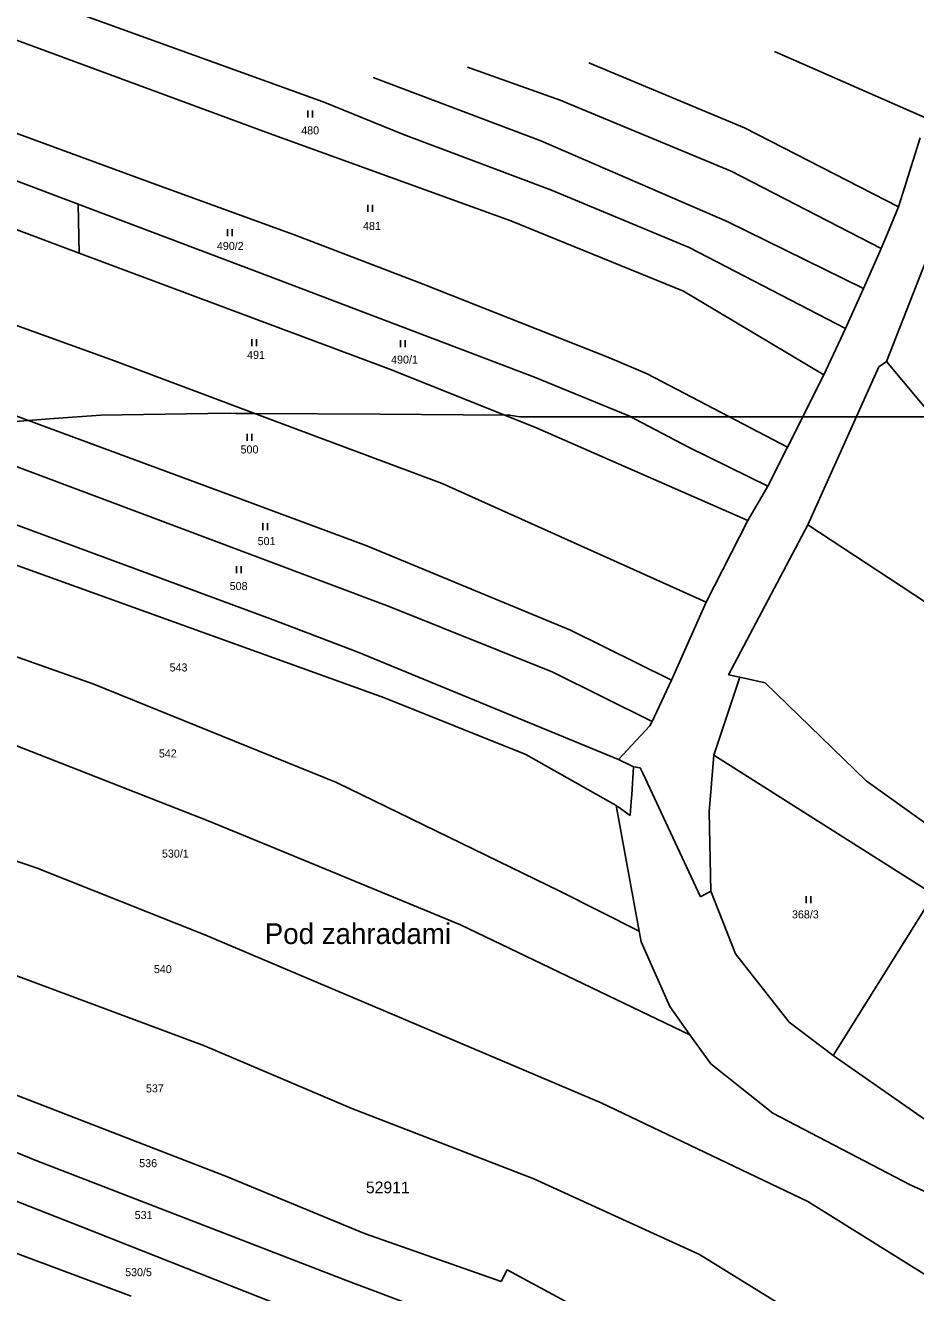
# Model space of a CAD drawing. Extents: x -749173 to -746119, y -1132678 to -1130338.
# Drawn here: x -748168.2 to -747979.1, y -1130971 to -1130701.9 of the extents above; entities that cross this region are included whole.
import ezdxf

# ---------------------------------------------------------------- set-up
doc = ezdxf.new("R2010")
doc.units = 0
for name, color, linetype in [('Vrstva 1', 7, 'Continuous'), ('Vrstva 15', 7, 'Continuous'), ('Vrstva 18', 7, 'Continuous'), ('Vrstva 25', 7, 'Continuous'), ('Vrstva 52', 7, 'Continuous'), ('Vrstva 53', 7, 'Continuous'), ('Vrstva 6', 7, 'Continuous')]:
    doc.layers.add(name, color=color, linetype=linetype)

msp = doc.modelspace()

# ---------------------------------------------------------------- linework, layer by layer
at = {"layer": 'Vrstva 1'}
for points in [[(-747978.13, -1130725.78), (-747981.47, -1130736.34)], [(-747968.32, -1130729.96), (-747985.28, -1130773.23)], [(-747981.47, -1130736.34), (-747982.76, -1130740.42)], [(-747982.76, -1130740.42), (-747984.75, -1130745.21)], [(-747984.75, -1130745.21), (-747986.44, -1130749.26)], [(-747986.44, -1130749.26), (-747987.1, -1130750.86)], [(-747987.1, -1130750.86), (-747990.16, -1130757.72)], [(-747990.16, -1130757.72), (-747994, -1130766.24)], [(-747994, -1130766.24), (-747998.62, -1130776.08)], [(-748001.98, -1130807.92), (-747986.9, -1130774.39)], [(-747986.9, -1130774.39), (-747985.28, -1130773.23)], [(-747937.23, -1130830.7), (-747985.28, -1130773.23)], [(-747998.62, -1130776.08), (-748006.3, -1130791.42)], [(-748006.3, -1130791.42), (-748010.51, -1130799.75)], [(-748116.18, -1130827.89), (-748206.22, -1130794.61)], [(-748010.51, -1130799.75), (-748014.77, -1130807.03)], [(-748023.6, -1130824.38), (-748014.77, -1130807.03)], [(-748001.98, -1130807.92), (-748018.82, -1130839.78)], [(-747959.65, -1130835.75), (-748001.98, -1130807.92)], [(-748171.55, -1130816.01), (-748091.95, -1130844.69)], [(-748023.6, -1130824.38), (-748030.93, -1130840.93)], [(-748097.77, -1130834.89), (-748116.18, -1130827.89)], [(-748042.25, -1130857.8), (-748097.77, -1130834.89)], [(-748030.93, -1130840.93), (-748035.09, -1130849.72)], [(-748016.47, -1130840.3), (-748021.96, -1130856.83)], [(-748018.82, -1130839.78), (-748016.47, -1130840.3)], [(-748016.47, -1130840.3), (-748011.06, -1130841.51)], [(-748011.06, -1130841.51), (-747989.61, -1130862.33)], [(-748091.95, -1130844.69), (-748061.9, -1130856.72)], [(-748035.09, -1130849.72), (-748035.54, -1130850.63)], [(-748035.54, -1130850.63), (-748042.25, -1130857.8)], [(-748061.9, -1130856.72), (-748042.73, -1130867.52)], [(-748039.61, -1130859.03), (-748042.25, -1130857.8)], [(-748022.97, -1130868.9), (-748021.96, -1130856.83)], [(-748021.96, -1130856.83), (-747975.23, -1130886.46)], [(-748039.02, -1130859.3), (-748039.61, -1130859.03)], [(-748039.41, -1130865.27), (-748039.02, -1130859.3)], [(-748039.02, -1130859.3), (-748037.61, -1130859.57)], [(-748037.61, -1130859.57), (-748037.08, -1130860.71)], [(-748037.08, -1130860.71), (-748024.8, -1130886.92)], [(-747989.61, -1130862.33), (-747963.27, -1130881.1)], [(-748039.51, -1130866.71), (-748039.41, -1130865.27)], [(-748042.73, -1130867.52), (-748037.84, -1130894.2)], [(-748042.73, -1130867.52), (-748042.31, -1130867.82)], [(-748042.31, -1130867.82), (-748039.71, -1130869.68)], [(-748039.71, -1130869.68), (-748039.51, -1130866.71)], [(-748022.6, -1130885.76), (-748022.97, -1130868.9)], [(-748024.8, -1130886.92), (-748022.6, -1130885.76)], [(-748017.39, -1130899.05), (-748022.6, -1130885.76)], [(-747975.23, -1130886.46), (-747996.61, -1130920.66)], [(-748037.84, -1130894.2), (-748037.41, -1130896.52)], [(-748037.41, -1130896.52), (-748031.35, -1130910.26)], [(-748005.97, -1130913.58), (-748017.39, -1130899.05)], [(-748031.35, -1130910.26), (-748027.06, -1130916.24)], [(-747996.61, -1130920.66), (-748005.97, -1130913.58)], [(-748027.06, -1130916.24), (-748022.64, -1130922.41)], [(-748009.46, -1130932.87), (-748022.64, -1130922.41)], [(-747996.61, -1130920.66), (-747974.9, -1130935.77)], [(-747980.23, -1130948.11), (-748009.46, -1130932.87)], [(-747943.32, -1130964.83), (-747980.23, -1130948.11)]]:
    msp.add_lwpolyline(points, dxfattribs=at)
at = {"layer": 'Vrstva 25'}
for p, q in [((-748108.25, -1130719.95), (-748108.25, -1130721.45)), ((-748107.25, -1130721.45), (-748107.25, -1130719.95)), ((-748095.46, -1130739.95), (-748095.46, -1130741.45)), ((-748094.46, -1130741.45), (-748094.46, -1130739.95)), ((-748125.27, -1130745.17), (-748125.27, -1130746.67)), ((-748124.27, -1130746.67), (-748124.27, -1130745.17)), ((-748120.1, -1130768.49), (-748120.1, -1130769.99)), ((-748119.1, -1130769.99), (-748119.1, -1130768.49)), ((-748088.55, -1130768.71), (-748088.55, -1130770.21)), ((-748087.55, -1130770.21), (-748087.55, -1130768.71)), ((-748121.1, -1130788.58), (-748121.1, -1130790.08)), ((-748120.1, -1130790.08), (-748120.1, -1130788.58)), ((-748117.77, -1130807.56), (-748117.77, -1130809.06)), ((-748116.77, -1130809.06), (-748116.77, -1130807.56)), ((-748123.4, -1130816.72), (-748123.4, -1130818.22)), ((-748122.4, -1130818.22), (-748122.4, -1130816.72)), ((-748002.37, -1130886.81), (-748002.37, -1130888.31)), ((-748001.37, -1130888.31), (-748001.37, -1130886.81))]:
    msp.add_line(p, q, dxfattribs=at)
at = {"layer": 'Vrstva 52'}
for points in [[(-748092.85, -1130784.45), (-748119.44, -1130784.28), (-748123.54, -1130784.26), (-748124.94, -1130784.25), (-748152.19, -1130784.62), (-748162.19, -1130785.36), (-748167.62, -1130785.76), (-748182.96, -1130786.89), (-748191.61, -1130787.52), (-748204.04, -1130788.43), (-748210, -1130788.87), (-748213.91, -1130789.71), (-748217.19, -1130790.42), (-748232.12, -1130793.62), (-748249.33, -1130798.12), (-748251.25, -1130798.62), (-748258.98, -1130801.59), (-748265.99, -1130804.29), (-748269.12, -1130805.5)], [(-747975.44, -1130785), (-747991.67, -1130785), (-748003.09, -1130785), (-748018.64, -1130785), (-748039.56, -1130785), (-748063.25, -1130785), (-748065.37, -1130784.62), (-748065.97, -1130784.62), (-748066.42, -1130784.62), (-748092.85, -1130784.45)]]:
    msp.add_lwpolyline(points, dxfattribs=at)
at = {"layer": 'Vrstva 6'}
for points in [[(-748116.35, -1130724.81), (-748185.93, -1130699.2)], [(-748104.99, -1130718.13), (-748160.68, -1130697.99)], [(-748009.08, -1130707.45), (-747977.16, -1130721.44)], [(-748015.48, -1130723.6), (-748048.51, -1130709.83)], [(-748094.37, -1130712.93), (-748058.72, -1130726.42)], [(-748074.3, -1130710.72), (-748054.6, -1130717.75)], [(-748192.08, -1130716.76), (-748141.67, -1130735.26)], [(-748087.93, -1130725.07), (-748104.99, -1130718.13)], [(-748054.6, -1130717.75), (-748018.25, -1130732.85)], [(-747982.76, -1130740.42), (-748015.48, -1130723.6)], [(-748065.1, -1130743.37), (-748116.35, -1130724.81)], [(-748056.46, -1130736.89), (-748087.93, -1130725.07)], [(-748058.72, -1130726.42), (-748019.1, -1130743.55)], [(-748172.71, -1130733.91), (-748157.04, -1130739.82)], [(-748018.25, -1130732.85), (-747986.44, -1130749.26)], [(-748141.67, -1130735.26), (-748110.72, -1130746.5)], [(-748027.2, -1130749.04), (-748056.46, -1130736.89)], [(-748186.46, -1130739.14), (-748156.81, -1130750.21)], [(-748157.04, -1130739.82), (-748116.12, -1130755.25)], [(-748157.04, -1130739.82), (-748156.81, -1130750.21)], [(-748028.39, -1130758.32), (-748065.1, -1130743.37)], [(-748019.1, -1130743.55), (-747990.16, -1130757.72)], [(-748110.72, -1130746.5), (-748083.73, -1130756.86)], [(-748156.81, -1130750.21), (-748090.98, -1130774.79)], [(-747994, -1130766.24), (-748027.2, -1130749.04)], [(-748116.12, -1130755.25), (-748060.06, -1130776.6)], [(-748149.26, -1130773.11), (-748192.95, -1130757.36)], [(-748083.73, -1130756.86), (-748044.13, -1130772.48)], [(-747998.62, -1130776.08), (-748028.39, -1130758.32)], [(-748124.83, -1130801.55), (-748198.84, -1130774.24)], [(-748117.42, -1130785.04), (-748149.26, -1130773.11)], [(-748090.98, -1130774.79), (-748059.97, -1130787.2)], [(-748044.13, -1130772.48), (-748036.15, -1130775.89)], [(-748060.06, -1130776.6), (-748040.01, -1130784.76)], [(-748036.15, -1130775.89), (-748006.3, -1130791.42)], [(-748202.3, -1130783.51), (-748146.21, -1130804.55)], [(-748079.7, -1130799.19), (-748117.42, -1130785.04)], [(-748040.01, -1130784.76), (-748027.38, -1130791.47)], [(-748059.97, -1130787.2), (-748014.77, -1130807.03)], [(-748027.38, -1130791.47), (-748010.51, -1130799.75)], [(-748023.6, -1130824.38), (-748079.7, -1130799.19)], [(-748095.68, -1130812.38), (-748124.83, -1130801.55)], [(-748146.21, -1130804.55), (-748090.95, -1130825.26)], [(-748052.4, -1130830.31), (-748095.68, -1130812.38)], [(-748090.95, -1130825.26), (-748056.18, -1130839.2)], [(-748030.93, -1130840.93), (-748052.4, -1130830.31)], [(-748178, -1130833.24), (-748153.66, -1130841.78)], [(-748056.18, -1130839.2), (-748035.09, -1130849.72)], [(-748153.66, -1130841.78), (-748102.13, -1130862.63)], [(-748129.42, -1130870.81), (-748173.97, -1130853.4)], [(-748102.13, -1130862.63), (-748054.55, -1130885.78)], [(-748206.84, -1130866.81), (-748165.74, -1130880.87)], [(-748112.36, -1130877.79), (-748129.42, -1130870.81)], [(-748075.79, -1130892.9), (-748112.36, -1130877.79)], [(-748165.74, -1130880.87), (-748130.12, -1130894.99)], [(-748054.55, -1130885.78), (-748037.84, -1130894.2)], [(-748130.17, -1130918.61), (-748198.42, -1130893.2)], [(-748027.06, -1130916.24), (-748075.79, -1130892.9)], [(-748130.12, -1130894.99), (-748094.02, -1130910.31)], [(-748094.02, -1130910.31), (-748045.92, -1130930.72)], [(-748098.9, -1130931.91), (-748130.17, -1130918.61)], [(-748187.39, -1130922.39), (-748125.51, -1130946.33)], [(-748208.52, -1130925.59), (-748165.81, -1130943.03)], [(-748156.11, -1130957.09), (-748225.28, -1130930)], [(-748045.92, -1130930.72), (-748002.03, -1130951.62)], [(-748060.2, -1130946.83), (-748098.9, -1130931.91)], [(-748165.81, -1130943.03), (-748099.08, -1130968.76)], [(-748125.51, -1130946.33), (-748096.2, -1130958.44)], [(-748025.01, -1130962.88), (-748060.2, -1130946.83)], [(-748002.03, -1130951.62), (-747975.69, -1130968.08)], [(-748188.9, -1130955.67), (-748145.76, -1130971.78)], [(-748105.93, -1130976.94), (-748156.11, -1130957.09)], [(-748096.2, -1130958.44), (-748067.15, -1130968.63)], [(-747986.3, -1130986.83), (-748025.01, -1130962.88)], [(-748099.08, -1130968.76), (-748070.08, -1130979.7)], [(-748067.15, -1130968.63), (-748065.85, -1130966.16)], [(-748065.85, -1130966.16), (-748020.12, -1130990.83)]]:
    msp.add_lwpolyline(points, dxfattribs=at)

# ---------------------------------------------------------------- texts
at = {"layer": 'Vrstva 15'}
msp.add_text('Pod zahradami', height=4.4, dxfattribs=at).set_placement((-748117.37, -1130896.96))
at = {"layer": 'Vrstva 18'}
for s, p in [('480', (-748109.62, -1130725.02)), ('481', (-748096.5, -1130745.32)), ('490/2', (-748127.54, -1130749.56)), ('491', (-748121.12, -1130772.69)), ('490/1', (-748090.53, -1130773.69)), ('500', (-748122.51, -1130792.78)), ('501', (-748118.88, -1130812.25)), ('508', (-748124.82, -1130821.79)), ('543', (-748137.59, -1130839.08)), ('542', (-748139.87, -1130857.34)), ('530/1', (-748139.21, -1130878.6)), ('368/3', (-748005.37, -1130891.52)), ('540', (-748140.93, -1130903.14)), ('537', (-748142.61, -1130928.47)), ('536', (-748144.04, -1130944.35)), ('531', (-748145.01, -1130955.37)), ('530/5', (-748147.03, -1130967.5))]:
    msp.add_text(s, height=1.7, dxfattribs=at).set_placement(p)
at = {"layer": 'Vrstva 53'}
msp.add_text('52911', height=2.5, dxfattribs=at).set_placement((-748095.88, -1130949.9))

doc.saveas('drawing.dxf')
